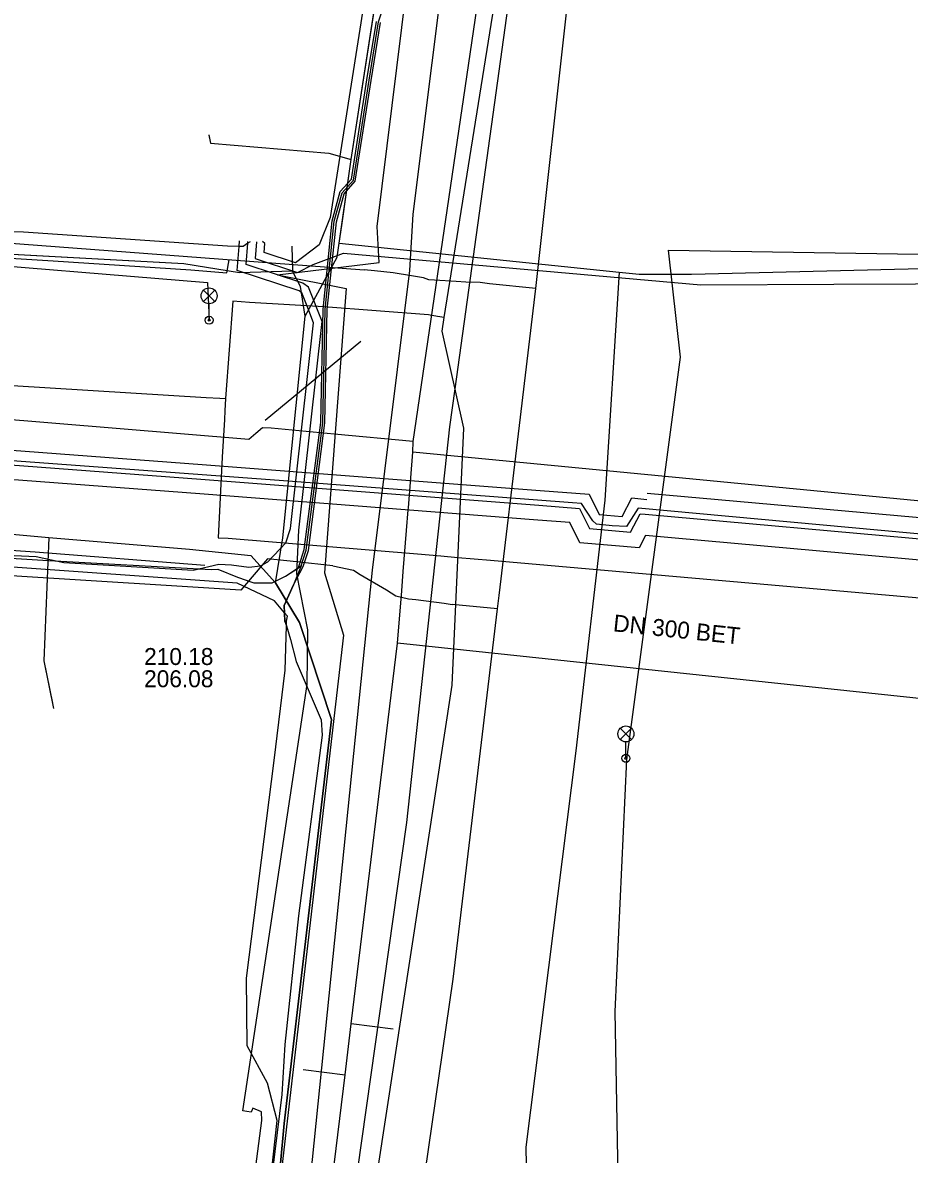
# Model space of a CAD drawing. Extents: x -596228 to -595156, y -1161235 to -1159373.
# Drawn here: x -595423.5 to -595381.6, y -1160980.9 to -1160927.5 of the extents above; entities that cross this region are included whole.
import ezdxf

# ---------------------------------------------------------------- set-up
doc = ezdxf.new("R2010")
doc.units = 0
for name, color, linetype in [('Vrstva 1', 7, 'Continuous'), ('Vrstva 12', 7, 'Continuous'), ('Vrstva 13', 7, 'Continuous'), ('Vrstva 14', 7, 'Continuous'), ('Vrstva 16', 7, 'Continuous'), ('Vrstva 19', 7, 'Continuous'), ('Vrstva 25', 7, 'Continuous'), ('Vrstva 26', 7, 'Continuous'), ('Vrstva 30', 7, 'Continuous'), ('Vrstva 33', 7, 'Continuous'), ('Vrstva 4', 7, 'Continuous'), ('Vrstva 42', 7, 'Continuous'), ('Vrstva 44', 7, 'Continuous'), ('Vrstva 55', 7, 'Continuous'), ('Vrstva 58', 7, 'Continuous'), ('Vrstva 9', 7, 'Continuous')]:
    doc.layers.add(name, color=color, linetype=linetype)

msp = doc.modelspace()

# ---------------------------------------------------------------- linework, layer by layer
at = {"layer": 'Vrstva 1'}
for p, q in [((-595407.531, -1160942.515), (-595412.038, -1160946.239)), ((-595379.64, -1160959.52), (-595405.794, -1160956.753))]:
    msp.add_line(p, q, dxfattribs=at)
at = {"layer": 'Vrstva 12'}
for p, q in [((-595407.98, -1160933.92), (-595405.64, -1160918.8)), ((-595408.43, -1160937.04), (-595407.98, -1160933.92)), ((-595408.55, -1160937.88), (-595408.43, -1160937.04)), ((-595410.78, -1160938.02), (-595410.75, -1160939.19)), ((-595429.32, -1160951.14), (-595422.25, -1160951.76))]:
    msp.add_line(p, q, dxfattribs=at)
for points in [[(-595414.7, -1160932.76), (-595414.63, -1160933.16), (-595409.03, -1160933.62), (-595407.98, -1160933.92)], [(-595408.55, -1160937.88), (-595395.33, -1160939.24), (-595396, -1160950.01), (-595397.37, -1160961.84), (-595399.73, -1160980.55), (-595399.67, -1160983.87), (-595399.46, -1160994.91), (-595399.35, -1161004.15), (-595400.01, -1161009.98), (-595401.51, -1161014.52), (-595416.36, -1161014.52)], [(-595410.16, -1160941.32), (-595408.64, -1160938.53), (-595408.55, -1160937.88)], [(-595410.75, -1160939.19), (-595413.26, -1160939.27), (-595415.89, -1160938.85), (-595424.57, -1160938.37)], [(-595410.16, -1160941.32), (-595410.38, -1160939.92), (-595410.75, -1160939.19)], [(-595411.56, -1160953.9), (-595411.21, -1160951.78), (-595410.16, -1160941.32)], [(-595422.25, -1160951.76), (-595422.49, -1160957.59), (-595422.03, -1160959.84)], [(-595422.25, -1160951.76), (-595415.62, -1160952.32), (-595412.72, -1160952.61), (-595411.56, -1160953.9)], [(-595411.56, -1160953.9), (-595410.42, -1160955.78), (-595408.91, -1160960.35), (-595411.14, -1160979.42), (-595411.5, -1160983.2), (-595411.94, -1160987.48)]]:
    msp.add_lwpolyline(points, dxfattribs=at)
at = {"layer": 'Vrstva 13'}
msp.add_lwpolyline([(-595395.33, -1160939.24), (-595394.39, -1160939.34), (-595391.91, -1160939.34), (-595370.82, -1160938.81), (-595370.01, -1160938.78)], dxfattribs=at)
at = {"layer": 'Vrstva 14'}
for p, q in [((-595403.586, -1160941.38), (-595403.9, -1160941.33)), ((-595414.18, -1160945.193), (-595413.91, -1160945.21)), ((-595413.91, -1160945.21), (-595413.947, -1160945.794)), ((-595413.79, -1160951.8), (-595404.852, -1160952.538)), ((-595401.404, -1160952.842), (-595366.99, -1160955.862))]:
    msp.add_line(p, q, dxfattribs=at)
for points in [[(-595411.29, -1161007.18), (-595405.35, -1160965.21), (-595403.324, -1160946.542), (-595403.072, -1160944.755), (-595398.92, -1160914.75), (-595397.23, -1160913.67), (-595395.51, -1160899.1), (-595392.712, -1160882.407), (-595392.622, -1160881.872)], [(-595403.586, -1160941.38), (-595401.229, -1160926.663), (-595399.42, -1160915.372), (-595397.797, -1160905.243), (-595396.846, -1160899.305), (-595396.485, -1160897.021), (-595394.65, -1160884.91)], [(-595412.78, -1160940.67), (-595413.565, -1160940.611), (-595413.91, -1160945.21)], [(-595403.9, -1160941.33), (-595404.335, -1160941.261), (-595409.277, -1160940.878), (-595412.78, -1160940.67)], [(-595411.27, -1161011.22), (-595410.586, -1161006.794), (-595409.337, -1160998.635), (-595407.872, -1160989.104), (-595403.214, -1160958.74), (-595402.67, -1160946.6), (-595403.689, -1160942.023), (-595403.586, -1160941.38)], [(-595455.494, -1160942.599), (-595448.863, -1160942.986), (-595445.255, -1160943.197), (-595444.18, -1160943.26), (-595433.861, -1160943.947), (-595427.951, -1160944.34), (-595427.47, -1160944.372), (-595426.45, -1160944.44), (-595425.767, -1160944.479), (-595414.825, -1160945.154), (-595414.18, -1160945.193)], [(-595413.947, -1160945.794), (-595413.97, -1160946.2), (-595414.07, -1160947.97), (-595414.27, -1160951.78), (-595413.79, -1160951.8)], [(-595404.852, -1160952.538), (-595403.747, -1160952.638), (-595402.942, -1160952.711), (-595401.404, -1160952.842)]]:
    msp.add_lwpolyline(points, dxfattribs=at)
at = {"layer": 'Vrstva 16'}
msp.add_lwpolyline([(-595410.61, -1160989.01), (-595406.97, -1160953.31), (-595405.21, -1160939.17), (-595405.06, -1160936.5), (-595403.71, -1160925.83), (-595403.705, -1160925.792), (-595402.346, -1160914.986), (-595402.25, -1160914.22), (-595402.1, -1160913.02), (-595401.46, -1160908.46), (-595400.96, -1160904.76), (-595400.56, -1160901.79), (-595400.16, -1160899.06), (-595399.71, -1160895.73), (-595398.29, -1160884.99)], dxfattribs=at)
at = {"layer": 'Vrstva 19'}
for p, q in [((-595399.27, -1160940.01), (-595401.45, -1160939.79)), ((-595401.07, -1160955.14), (-595403.22, -1160954.92))]:
    msp.add_line(p, q, dxfattribs=at)
for points in [[(-595407.87, -1160994.73), (-595407.55, -1160991.2), (-595406.3, -1160990.26), (-595405.66, -1160989.78), (-595403.17, -1160972.62), (-595401.07, -1160955.14), (-595400.99, -1160954.5), (-595400.04, -1160946.48), (-595399.27, -1160940.01), (-595397.73, -1160926.27), (-595396.38, -1160915.92), (-595396.07, -1160913.72), (-595395.07, -1160906.51), (-595394.24, -1160900.25), (-595393.67, -1160895.74), (-595393.31, -1160893.43), (-595394.75, -1160891.58)], [(-595539.39, -1160930.21), (-595521.57, -1160931.46), (-595517.53, -1160931.69), (-595508.33, -1160932.29), (-595499.58, -1160932.86), (-595478.69, -1160934.25), (-595472.03, -1160934.56), (-595461.91, -1160935.48), (-595457.81, -1160935.75), (-595453.76, -1160935.96), (-595453.529, -1160935.971), (-595453.31, -1160936), (-595442.81, -1160936.68), (-595426.15, -1160937.72), (-595407.365, -1160939.13)], [(-595402.571, -1160939.721), (-595403.023, -1160939.684), (-595404.042, -1160939.617), (-595404.32, -1160939.598), (-595404.561, -1160939.515), (-595405.14, -1160939.42), (-595406, -1160939.279), (-595406.877, -1160939.177), (-595407.365, -1160939.13)], [(-595401.45, -1160939.79), (-595401.89, -1160939.73), (-595402.571, -1160939.721)], [(-595408.847, -1160953.104), (-595410.558, -1160952.919), (-595411.93, -1160952.77), (-595413.19, -1160954.25), (-595423.53, -1160953.61), (-595434.15, -1160952.91), (-595444.27, -1160952.09), (-595455.3, -1160951.31), (-595457.7, -1160951.15), (-595475.55, -1160949.99), (-595477.61, -1160949.95), (-595497.09, -1160948.59), (-595505.61, -1160948.16), (-595519.4, -1160947.21), (-595526.65, -1160946.74), (-595540.96, -1160945.75), (-595550.77, -1160945.01), (-595555.89, -1160944.62), (-595579.85, -1160943.09), (-595594.69, -1160942.04), (-595614.611, -1160940.715), (-595614.601, -1160940.513)], [(-595408.847, -1160953.104), (-595407.865, -1160953.301), (-595407.563, -1160953.507), (-595406.312, -1160954.242), (-595405.876, -1160954.516), (-595405.278, -1160954.658), (-595404.936, -1160954.699), (-595403.596, -1160954.871), (-595403.22, -1160954.92)]]:
    msp.add_lwpolyline(points, dxfattribs=at)
at = {"layer": 'Vrstva 25'}
msp.add_line((-595394.096, -1160950.669), (-595369.825, -1160952.84), dxfattribs=at)
for points in [[(-595779.494, -1160891.049), (-595764.267, -1160890.72), (-595748.814, -1160890.287), (-595748.85, -1160887.319), (-595745.169, -1160887.204), (-595745.059, -1160889.778), (-595709.422, -1160888.719), (-595665.367, -1160887.377), (-595623.951, -1160886.18), (-595622.034, -1160913.547), (-595620.641, -1160935.64), (-595593.938, -1160937.219), (-595551.734, -1160939.776), (-595498.958, -1160943.096), (-595433.268, -1160947.644), (-595415.079, -1160949.013), (-595399.116, -1160950.243)], [(-595399.116, -1160950.243), (-595397.2, -1160950.39), (-595396.731, -1160951.347), (-595394.786, -1160951.512), (-595394.332, -1160950.644), (-595394.096, -1160950.669)]]:
    msp.add_lwpolyline(points, dxfattribs=at)
at = {"layer": 'Vrstva 26'}
for p, q in [((-595394.007, -1160949.673), (-595369.736, -1160951.844)), ((-595369.914, -1160953.836), (-595394.081, -1160951.674))]:
    msp.add_line(p, q, dxfattribs=at)
for points in [[(-595778.996, -1160890.338), (-595764.284, -1160890.021), (-595749.522, -1160889.606), (-595749.559, -1160886.64), (-595744.5, -1160886.483), (-595744.389, -1160889.058), (-595709.443, -1160888.019), (-595665.388, -1160886.677), (-595623.299, -1160885.461), (-595621.335, -1160913.501), (-595619.981, -1160934.978), (-595593.896, -1160936.52), (-595551.691, -1160939.078), (-595498.912, -1160942.398), (-595433.217, -1160946.946), (-595415.025, -1160948.315), (-595399.062, -1160949.545)], [(-595399.169, -1160950.941), (-595415.132, -1160949.711), (-595433.318, -1160948.342), (-595499.004, -1160943.795), (-595551.777, -1160940.475), (-595593.98, -1160937.918), (-595621.3, -1160936.303), (-595622.732, -1160913.594), (-595624.602, -1160886.899), (-595665.347, -1160888.077), (-595709.401, -1160889.419), (-595745.729, -1160890.499), (-595745.839, -1160887.925), (-595748.142, -1160887.997), (-595748.106, -1160890.967), (-595764.249, -1160891.42), (-595779.478, -1160891.749)], [(-595399.062, -1160949.545), (-595396.747, -1160949.723), (-595396.277, -1160950.683), (-595395.191, -1160950.775), (-595394.732, -1160949.897), (-595394.022, -1160949.973)], [(-595394.081, -1160951.674), (-595394.382, -1160952.248), (-595397.186, -1160952.011), (-595397.652, -1160951.058), (-595399.169, -1160950.941)]]:
    msp.add_lwpolyline(points, dxfattribs=at)
at = {"layer": 'Vrstva 30'}
msp.add_lwpolyline([(-595375.771, -1160952.1), (-595394.433, -1160950.38), (-595394.975, -1160951.241), (-595395.666, -1160951.215), (-595396.394, -1160951.131), (-595396.568, -1160950.986), (-595397.114, -1160950.167), (-595397.535, -1160950.126), (-595410.955, -1160949.099), (-595439.805, -1160946.979), (-595466.158, -1160945.12), (-595495.623, -1160943.053), (-595544.466, -1160939.982), (-595596.132, -1160936.829), (-595620.319, -1160935.355), (-595620.406, -1160935.005), (-595620.828, -1160927.419), (-595622.823, -1160898.786), (-595623.664, -1160886.374), (-595623.331, -1160885.169), (-595624.205, -1160885.915), (-595655.406, -1160886.792), (-595709.181, -1160888.443)], dxfattribs=at)
at = {"layer": 'Vrstva 33'}
for p, q in [((-595414.955, -1160940.095), (-595414.425, -1160940.625)), ((-595414.955, -1160940.625), (-595414.425, -1160940.095)), ((-595414.69, -1160941.51), (-595414.69, -1160940.735)), ((-595395.275, -1160960.772), (-595394.745, -1160961.302)), ((-595395.275, -1160961.302), (-595394.745, -1160960.772)), ((-595395.01, -1160962.187), (-595395.01, -1160961.412))]:
    msp.add_line(p, q, dxfattribs=at)
for centre, radius in [((-595414.69, -1160940.36), 0.375), ((-595414.69, -1160941.51), 0.19), ((-595414.69, -1160941.51), 0.05), ((-595395.01, -1160961.037), 0.375), ((-595395.01, -1160962.187), 0.19), ((-595395.01, -1160962.187), 0.05)]:
    msp.add_circle(centre, radius, dxfattribs=at)
at = {"layer": 'Vrstva 42'}
for points in [[(-595400.818, -1160883.719), (-595402.568, -1160894.603), (-595403.11, -1160894.98), (-595402.683, -1160895.634), (-595403.025, -1160897.539), (-595405.444, -1160914.819), (-595405.66, -1160915.124), (-595405.945, -1160915.248), (-595405.678, -1160915.523), (-595405.687, -1160915.76), (-595408.98, -1160936.668), (-595409.496, -1160937.954), (-595410.61, -1160938.804), (-595412.096, -1160938.317), (-595412.062, -1160937.892), (-595412.167, -1160937.798)], [(-595375.771, -1160952.1), (-595394.433, -1160950.38), (-595394.975, -1160951.241), (-595395.666, -1160951.215), (-595396.394, -1160951.131), (-595396.568, -1160950.986), (-595397.114, -1160950.167), (-595397.535, -1160950.126), (-595410.955, -1160949.099), (-595439.805, -1160946.979), (-595466.158, -1160945.12), (-595495.623, -1160943.053), (-595544.466, -1160939.982), (-595596.132, -1160936.829), (-595620.319, -1160935.355), (-595620.406, -1160935.005), (-595620.828, -1160927.419), (-595622.823, -1160898.786), (-595623.664, -1160886.374), (-595623.331, -1160885.169), (-595624.205, -1160885.915), (-595655.406, -1160886.792), (-595709.181, -1160888.443)], [(-595412.757, -1160937.809), (-595412.863, -1160937.88), (-595413.087, -1160938.029), (-595413.276, -1160938.024), (-595413.827, -1160938.009), (-595423.457, -1160937.349), (-595424.957, -1160937.309), (-595427.086, -1160937.098), (-595427.657, -1160937.079), (-595427.797, -1160936.749), (-595428.217, -1160937.079), (-595428.657, -1160937.179), (-595430.997, -1160936.859), (-595431.527, -1160936.489), (-595432.047, -1160936.789), (-595437.247, -1160936.449), (-595441.577, -1160936.139), (-595443.207, -1160936.109), (-595447.487, -1160935.839), (-595450.267, -1160935.619), (-595450.577, -1160935.259), (-595450.997, -1160935.629), (-595453.627, -1160935.449)], [(-595458.388, -1160936.218), (-595450.742, -1160936.682), (-595443.735, -1160937.171), (-595440.632, -1160937.414), (-595437.482, -1160937.661), (-595429.594, -1160938.239), (-595422.055, -1160938.702), (-595415.546, -1160939.135), (-595413.846, -1160939.271), (-595413.74, -1160938.663)], [(-595414.279, -1160995.188), (-595412.207, -1160979.288), (-595412.215, -1160978.872), (-595412.63, -1160978.706), (-595412.707, -1160978.886), (-595412.907, -1160978.86), (-595413.097, -1160978.833), (-595410.067, -1160958.704), (-595410.034, -1160956.127), (-595410.542, -1160953.476), (-595410.447, -1160951.412), (-595409.346, -1160941.572), (-595409.991, -1160939.955), (-595410.26, -1160939.76), (-595412.943, -1160938.882), (-595412.863, -1160937.88), (-595412.856, -1160937.786)], [(-595413.627, -1160953.049), (-595412.817, -1160953.169), (-595412.266, -1160953.103), (-595411.924, -1160952.91), (-595411.074, -1160952.015), (-595410.841, -1160951.342), (-595409.754, -1160941.628), (-595410.036, -1160940.92), (-595410.319, -1160940.211), (-595410.443, -1160940.121), (-595413.367, -1160939.164), (-595413.276, -1160938.024), (-595413.255, -1160937.756)], [(-595412.458, -1160937.816), (-595412.52, -1160938.6), (-595410.509, -1160939.258), (-595409.781, -1160938.884), (-595408.35, -1160938.352), (-595391.478, -1160939.84), (-595385.196, -1160939.809), (-595381.329, -1160939.79), (-595371.367, -1160939.639), (-595370.742, -1160940.089), (-595370.027, -1160942.079), (-595369.304, -1160948.18), (-595369.392, -1160955.891), (-595369.325, -1160956.272), (-595369.085, -1160956.98)], [(-595452.657, -1160951.109), (-595443.357, -1160951.679), (-595443.09, -1160952.114), (-595443.061, -1160952.527), (-595442.947, -1160952.719), (-595442.861, -1160952.512), (-595442.888, -1160952.132), (-595442.697, -1160951.769), (-595442.067, -1160951.669), (-595442.01, -1160951.673), (-595441.731, -1160951.692), (-595437.757, -1160951.969), (-595431.927, -1160952.259), (-595422.857, -1160952.659), (-595421.557, -1160952.949), (-595415.437, -1160953.309), (-595414.237, -1160953.019), (-595413.627, -1160953.049)], [(-595438.798, -1160951.592), (-595436.832, -1160951.681), (-595431.425, -1160951.867), (-595422.896, -1160952.443), (-595414.888, -1160953.071)]]:
    msp.add_lwpolyline(points, dxfattribs=at)
at = {"layer": 'Vrstva 44'}
for points in [[(-595413.35, -1160953.63), (-595412.58, -1160953.91), (-595411.71, -1160953.9), (-595411.08, -1160953.59), (-595410.472, -1160953.196), (-595410.435, -1160953.08), (-595410.198, -1160952.338), (-595409.42, -1160946.342), (-595409.31, -1160940.994), (-595408.879, -1160936.822), (-595408.5, -1160935.441), (-595407.974, -1160934.855), (-595407.239, -1160930.164), (-595406.787, -1160927.406)], [(-595411.11, -1160955.73), (-595411.132, -1160955.316), (-595411.15, -1160954.97), (-595410.71, -1160954), (-595410.245, -1160953.14), (-595410.002, -1160952.382), (-595409.22, -1160946.357), (-595409.11, -1160941.006), (-595408.681, -1160936.858), (-595408.32, -1160935.539), (-595407.786, -1160934.945), (-595407.041, -1160930.196), (-595406.593, -1160927.454)], [(-595530.577, -1160945.689), (-595521.539, -1160946.285), (-595514.346, -1160946.759), (-595503.777, -1160947.399), (-595489.807, -1160948.449), (-595481.477, -1160948.949), (-595475.496, -1160949.229), (-595467.587, -1160949.899), (-595456.637, -1160950.619), (-595443.277, -1160951.469), (-595437.347, -1160951.929), (-595431.927, -1160952.259), (-595422.537, -1160952.839), (-595414.587, -1160953.269), (-595414.28, -1160953.26), (-595413.35, -1160953.63)], [(-595412.027, -1160984.331), (-595411.484, -1160979.288), (-595411.925, -1160977.521), (-595412.9, -1160975.767), (-595412.923, -1160972.573), (-595411.614, -1160962.293), (-595411.102, -1160958.024), (-595411.043, -1160955.941), (-595411.037, -1160955.719), (-595410.994, -1160955.484), (-595411.132, -1160955.316), (-595411.596, -1160954.75), (-595413.363, -1160953.924), (-595425.075, -1160953.08), (-595436.866, -1160952.205), (-595447.914, -1160951.444), (-595459.486, -1160950.567)], [(-595411.11, -1160955.73), (-595411.043, -1160955.941), (-595410.84, -1160956.58), (-595410.574, -1160957.618), (-595409.397, -1160960.369), (-595409.347, -1160961.089), (-595410.467, -1160969.629), (-595411.117, -1160975.689), (-595411.257, -1160978.059), (-595412.027, -1160984.331), (-595412.167, -1160985.469), (-595413.117, -1160992.149)]]:
    msp.add_lwpolyline(points, dxfattribs=at)
at = {"layer": 'Vrstva 55'}
for points in [[(-595411.46, -1160939.37), (-595406.666, -1160938.79), (-595406.76, -1160937.08), (-595400.21, -1160884.27), (-595402.02, -1160882.46), (-595413.593, -1160883.169), (-595423.46, -1160882.73)], [(-595453.69, -1160937.07), (-595451.22, -1160937.05), (-595443.44, -1160938.09), (-595443.08, -1160939.37), (-595443.44, -1160938.09), (-595432.22, -1160938.37), (-595431.56, -1160938.34), (-595428.65, -1160938.47), (-595428.18, -1160938.63), (-595414.76, -1160939.73), (-595414.69, -1160941.51)], [(-595401.12, -1161017.19), (-595396.08, -1161009.89), (-595394.21, -1160998.66), (-595395.259, -1160988.029), (-595395.52, -1160974.14), (-595394.961, -1160962.237), (-595392.43, -1160943.26), (-595393, -1160938.21), (-595369.41, -1160938.58), (-595362.11, -1160937.46), (-595359.3, -1160943.45), (-595359.87, -1160953.93), (-595366.79, -1160953.56), (-595367.1, -1160959.08), (-595366.535, -1160960.59), (-595368.38, -1160960.57)], [(-595411.46, -1160939.37), (-595408.22, -1160940.01), (-595409.24, -1160953.44), (-595408.34, -1160956.38), (-595414.09, -1161005.92), (-595416.42, -1161006.03)]]:
    msp.add_lwpolyline(points, dxfattribs=at)
at = {"layer": 'Vrstva 58'}
msp.add_line((-595429.32, -1160951.14), (-595422.25, -1160951.76), dxfattribs=at)
for points in [[(-595411.5, -1160983.2), (-595411.14, -1160979.42), (-595408.91, -1160960.35), (-595410.42, -1160955.78), (-595411.56, -1160953.9), (-595411.21, -1160951.78), (-595410.16, -1160941.32), (-595408.64, -1160938.53), (-595407.98, -1160933.92), (-595405.58, -1160918.39), (-595404.98, -1160914.76), (-595403.22, -1160903.59), (-595402.29, -1160897.41), (-595401.59, -1160891.85), (-595400.62, -1160884.65), (-595400.75, -1160882.05), (-595400.27, -1160875.03), (-595402.22, -1160875.2), (-595411.71, -1160875.61), (-595420.37, -1160876), (-595429.24, -1160876.32), (-595436.21, -1160876.71), (-595440.47, -1160876.95)], [(-595410.34, -1160953.11), (-595410.1, -1160952.36), (-595409.32, -1160946.35), (-595409.21, -1160941), (-595408.78, -1160936.84), (-595408.41, -1160935.49), (-595407.88, -1160934.9), (-595407.14, -1160930.18), (-595406.69, -1160927.43), (-595406.42, -1160926.62), (-595406.14, -1160925.12), (-595405.34, -1160920.12), (-595404.39, -1160914.08), (-595403.89, -1160910.76), (-595403.65, -1160908.69), (-595403.25, -1160905.88), (-595403.02, -1160904.39), (-595402.61, -1160902.45), (-595402.23, -1160900.11), (-595402.03, -1160898.6), (-595401.52, -1160895.51), (-595401.36, -1160894.02), (-595400.5, -1160887.93)], [(-595407.98, -1160933.92), (-595405.58, -1160918.39), (-595404.98, -1160914.76)], [(-595414.7, -1160932.77), (-595414.63, -1160933.16), (-595409.03, -1160933.62), (-595407.98, -1160933.92)], [(-595410.16, -1160941.32), (-595408.64, -1160938.53), (-595407.98, -1160933.92)], [(-595410.75, -1160939.19), (-595413.26, -1160939.27), (-595415.89, -1160938.85), (-595424.58, -1160938.37)], [(-595411.56, -1160953.9), (-595411.21, -1160951.78), (-595410.16, -1160941.32), (-595410.38, -1160939.92), (-595410.75, -1160939.19)], [(-595422.25, -1160951.76), (-595422.49, -1160957.59), (-595422.08, -1160959.59)], [(-595422.25, -1160951.76), (-595415.62, -1160952.32), (-595412.72, -1160952.61), (-595411.56, -1160953.9)], [(-595413.35, -1160953.63), (-595412.58, -1160953.91), (-595411.71, -1160953.9), (-595411.08, -1160953.59), (-595410.34, -1160953.11)], [(-595410.34, -1160953.11), (-595410.71, -1160954), (-595411.15, -1160954.97), (-595411.11, -1160955.73)], [(-595411.56, -1160953.9), (-595410.42, -1160955.78), (-595408.91, -1160960.35), (-595411.14, -1160979.42), (-595411.5, -1160983.2), (-595411.94, -1160987.48)]]:
    msp.add_lwpolyline(points, dxfattribs=at)
at = {"layer": 'Vrstva 9'}
for p, q in [((-595405.057, -1160947.229), (-595400.58, -1160916.76)), ((-595405.067, -1160947.744), (-595405.057, -1160947.229)), ((-595379.773, -1160950.169), (-595405.067, -1160947.744)), ((-595405.994, -1160974.969), (-595407.979, -1160974.728)), ((-595410.255, -1160976.88), (-595408.27, -1160977.121))]:
    msp.add_line(p, q, dxfattribs=at)
for points in [[(-595412.486, -1160946.858), (-595412.808, -1160947.135), (-595425.177, -1160946.115), (-595425.244, -1160946.11), (-595427.221, -1160945.947), (-595427.337, -1160945.937), (-595430.797, -1160945.652), (-595430.845, -1160945.648), (-595443.08, -1160944.64), (-595443.213, -1160944.629), (-595446.791, -1160944.334), (-595446.793, -1160944.334), (-595447.817, -1160944.249), (-595447.881, -1160944.244), (-595448.824, -1160944.166), (-595448.894, -1160944.16), (-595449.99, -1160944.07)], [(-595405.057, -1160947.229), (-595408.779, -1160946.886), (-595411.766, -1160946.611), (-595412.164, -1160946.581), (-595412.486, -1160946.858)], [(-595405.794, -1160956.753), (-595405.595, -1160954.288), (-595405.522, -1160953.37), (-595405.365, -1160951.434), (-595405.288, -1160950.456), (-595405.279, -1160950.367), (-595405.067, -1160947.744)], [(-595410.563, -1160995.982), (-595410.152, -1160992.597), (-595410.04, -1160991.674), (-595409.874, -1160990.314), (-595409.367, -1160986.144), (-595408.901, -1160982.313), (-595408.865, -1160982.015), (-595408.27, -1160977.121), (-595407.979, -1160974.728), (-595405.794, -1160956.753)]]:
    msp.add_lwpolyline(points, dxfattribs=at)

# ---------------------------------------------------------------- texts
at = {"layer": 'Vrstva 12'}
for s, p in [('210.18', (-595417.759, -1160957.783)), ('206.08', (-595417.759, -1160958.833))]:
    msp.add_text(s, height=0.8, dxfattribs=at).set_placement(p)
at = {"layer": 'Vrstva 4'}
msp.add_text('DN 300 BET', height=0.8, rotation=354, dxfattribs=at).set_placement((-595395.64, -1160956.189))

doc.saveas('drawing.dxf')
